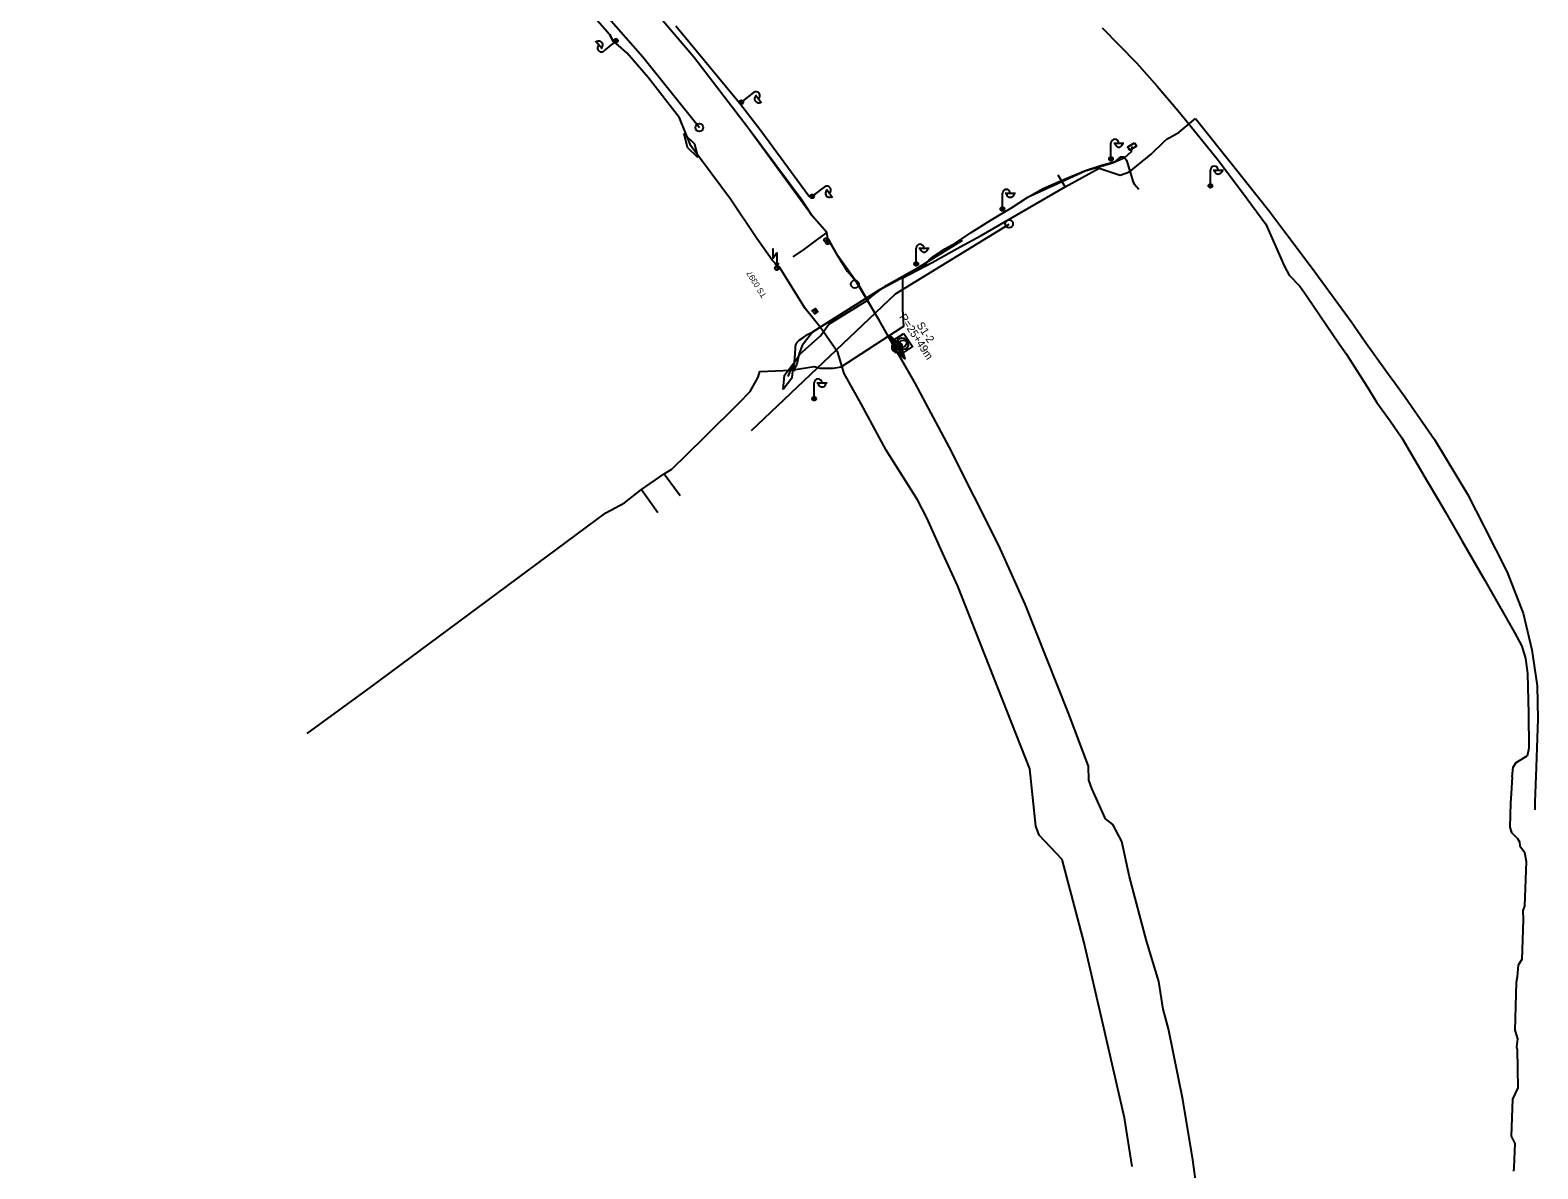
# Model space of a CAD drawing. Extents: x -748507 to -687366, y -1057342 to -1024924.
# Drawn here: x -744119.8 to -743736.3, y -1038215.5 to -1037925.9 of the extents above; entities that cross this region are included whole.
import ezdxf

# ---------------------------------------------------------------- set-up
doc = ezdxf.new("R2010")
doc.units = 0
for name, color, linetype in [('6kV - SŽDC', 7, 'Continuous'), ('DK + TKK - SŽDC', 7, 'Continuous'), ('Kanalizace - pražské vodovody a kanalizace', 7, 'Continuous'), ('kanalizace ČD', 7, 'Continuous'), ('PRE - NN', 7, 'Continuous'), ('PRE - VN', 7, 'Continuous'), ('STL - PRAŽSKÁ PLYNÁRENSKÁ', 7, 'Continuous'), ('TK+DOK_Pha Holešovice - Kralupy', 7, 'Continuous'), ('Vedení NN - SŽDC', 7, 'Continuous'), ('ČD-Telematika_DK+TKK', 7, 'Continuous')]:
    doc.layers.add(name, color=color, linetype=linetype)

msp = doc.modelspace()

# ---------------------------------------------------------------- linework, layer by layer
at = {"layer": '6kV - SŽDC'}
for p, q in [((-743930.89, -1037981.43), (-743930.89, -1037983.93)), ((-743930.89, -1037983.93), (-743929.89, -1037982.43)), ((-743929.89, -1037982.43), (-743929.89, -1037985.93)), ((-743930.39, -1037985.03), (-743929.89, -1037985.93)), ((-743929.94, -1037986.43), (-743929.84, -1037986.43)), ((-743929.89, -1037985.93), (-743929.39, -1037985.03))]:
    msp.add_line(p, q, dxfattribs=at)
for points in [[(-743989.74, -1037907.17), (-743972.42, -1037926.86), (-743971.51, -1037928.66), (-743970.83, -1037928.59)], [(-743929.38, -1037986.08), (-743931.03, -1037984.4), (-743934.99, -1037978.89), (-743941.71, -1037968.88), (-743951.72, -1037955.26), (-743954.61, -1037948.2), (-743962.61, -1037937.94), (-743968.04, -1037931.62), (-743970.13, -1037929.74), (-743971.51, -1037928.66), (-743972.42, -1037926.86)], [(-743950.01, -1037958.31), (-743952.59, -1037955.75), (-743953.43, -1037952.21), (-743950.85, -1037954.77), (-743950.01, -1037958.31)], [(-743857.28, -1038136.85), (-743863.19, -1038130.67), (-743864.02, -1038128.37), (-743865.55, -1038113.76), (-743883.85, -1038067.27), (-743887.69, -1038059), (-743891.71, -1038049.93), (-743894.08, -1038045.32), (-743902.07, -1038032.69), (-743908.42, -1038020.92), (-743912.76, -1038013.22), (-743914.38, -1038007.84), (-743918.81, -1038001.48), (-743922.64, -1037996.66), (-743929.22, -1037986.18), (-743929.38, -1037986.08), (-743929.89, -1037986.43)], [(-743839.49, -1038214.96), (-743841.42, -1038202.51), (-743846.96, -1038178.59), (-743851.76, -1038158.03), (-743857.28, -1038136.85)]]:
    msp.add_lwpolyline(points, dxfattribs=at)
msp.add_circle((-743929.89, -1037986.43), 0.5, dxfattribs=at)
at = {"layer": 'DK + TKK - SŽDC'}
for p, q in [((-743917.4, -1037979.26), (-743917.3, -1037979.26)), ((-743917, -1037979.83), (-743916.9, -1037979.83))]:
    msp.add_line(p, q, dxfattribs=at)
for points in [[(-743917.13, -1037977.37), (-743920.94, -1037973.08), (-743923.44, -1037969.18), (-743937.32, -1037950.58), (-743951, -1037932.72), (-743961.3, -1037920.58)], [(-743916.89, -1037978.84), (-743917.13, -1037977.37), (-743919.84, -1037979.33), (-743922.93, -1037981.61), (-743925.83, -1037983.52)], [(-743916.89, -1037978.84), (-743917.35, -1037979.26)], [(-743916.52, -1037979.46), (-743916.95, -1037979.83)], [(-743873.45, -1038056.97), (-743885.94, -1038032.02), (-743894.72, -1038015.69), (-743903.85, -1037999.61), (-743909.08, -1037990.51), (-743909.69, -1037989.77), (-743911.87, -1037987.29), (-743914.4, -1037983.29), (-743916.52, -1037979.46), (-743916.89, -1037978.84)], [(-743831.59, -1038174.87), (-743832.72, -1038167.9), (-743835.86, -1038157.49), (-743840.18, -1038141.25), (-743842.11, -1038132.25), (-743844.44, -1038127.94), (-743846.27, -1038126.48), (-743849.8, -1038118.78), (-743850.55, -1038116.65), (-743850.63, -1038113.07), (-743855.68, -1038099.64), (-743866.71, -1038071.91), (-743873.45, -1038056.97)], [(-743817.1, -1038311.81), (-743817.13, -1038284.47), (-743817.99, -1038274.76), (-743819.12, -1038254.08), (-743820.54, -1038239.39), (-743824.11, -1038213.21), (-743826.65, -1038197.89), (-743830.31, -1038179.92), (-743831.59, -1038174.87)]]:
    msp.add_lwpolyline(points, dxfattribs=at)
for centre in [(-743917.35, -1037979.26), (-743916.95, -1037979.83)]:
    msp.add_circle(centre, 0.5, dxfattribs=at)
at = {"layer": 'Kanalizace - pražské vodovody a kanalizace'}
for p, q in [((-743899.68, -1037992.92), (-743870.82, -1037975.21)), ((-743936.35, -1038027.75), (-743899.68, -1037992.92))]:
    msp.add_line(p, q, dxfattribs=at)
at = {"layer": 'kanalizace ČD'}
for points in [[(-743949.52, -1037950.73), (-743963.98, -1037932.73), (-743980.01, -1037914.41), (-744006.76, -1037884.28), (-744040.1, -1037846.82), (-744073.37, -1037809.61), (-744104.79, -1037774.57), (-744106.99, -1037773.74), (-744108.26, -1037772.24), (-744108.47, -1037770.54), (-744119.79, -1037757.39)], [(-743919.85, -1037997.74), (-743920.24, -1037998.05), (-743920.86, -1037997.26), (-743920.08, -1037996.64), (-743919.46, -1037997.43), (-743919.85, -1037997.74), (-743920.47, -1037996.95)]]:
    msp.add_lwpolyline(points, dxfattribs=at)
for centre in [(-743949.59, -1037950.66), (-743870.82, -1037975.14), (-743910.04, -1037990.49)]:
    msp.add_circle(centre, 1, dxfattribs=at)
at = {"layer": 'PRE - NN'}
msp.add_lwpolyline([(-743892.02, -1037985.3), (-743893.69, -1037986.34), (-743894.53, -1037986.89), (-743903.77, -1037991.96), (-743920.7, -1038002.64), (-743922.31, -1038004.63), (-743923.42, -1038006.13), (-743924.23, -1038008.12), (-743924.83, -1038010.81), (-743925.27, -1038011.83), (-743925.57, -1038012.62)], dxfattribs=at)
at = {"layer": 'PRE - VN'}
msp.add_lwpolyline([(-743925.57, -1038012.62), (-743925.22, -1038008.25), (-743925.17, -1038006.67), (-743925.01, -1038005.76), (-743924.74, -1038005.22), (-743924.19, -1038004.71), (-743923.04, -1038004.01), (-743922.11, -1038003.32), (-743920.7, -1038002.64), (-743903.77, -1037991.96), (-743894.53, -1037986.89), (-743892.02, -1037985.3), (-743891.1, -1037984.31), (-743889.98, -1037983.33), (-743887.17, -1037981.48), (-743884.4, -1037980), (-743880.47, -1037977.38), (-743875.48, -1037974.2), (-743870.17, -1037971.04), (-743866.08, -1037968.38), (-743862.16, -1037966.18), (-743856.29, -1037963.57), (-743852.85, -1037962.16), (-743851.6, -1037961.67), (-743847.21, -1037960.18), (-743844.72, -1037959.57), (-743843.69, -1037959.18), (-743842.39, -1037958.09), (-743841.65, -1037958.11), (-743840.93, -1037958.97), (-743839.29, -1037964.56), (-743839.03, -1037964.98), (-743837.85, -1037966.29)], dxfattribs=at)
at = {"layer": 'STL - PRAŽSKÁ PLYNÁRENSKÁ'}
for p, q in [((-743856.54, -1037965.71), (-743858.32, -1037962.8)), ((-743958.55, -1038038.74), (-743954.48, -1038044.28)), ((-743964.3, -1038042.75), (-743960.19, -1038048.54))]:
    msp.add_line(p, q, dxfattribs=at)
for points in [[(-743956.62, -1038037.51), (-743952.7, -1038033.69), (-743948.13, -1038029.27), (-743939.44, -1038020.67), (-743936.7, -1038017.8), (-743934.61, -1038014.18), (-743934.19, -1038012.71), (-743926.27, -1038012.36), (-743920.43, -1038011.4), (-743918.88, -1038011.83), (-743915.57, -1038011.83), (-743913.53, -1038011.49), (-743898.03, -1038001.46), (-743897.61, -1038001.19), (-743897.68, -1038000), (-743897.86, -1037996.76), (-743897.82, -1037990.96), (-743897.81, -1037988.87), (-743890.34, -1037984.97), (-743883.23, -1037980.98), (-743877.91, -1037978.12), (-743856.54, -1037965.71), (-743847.88, -1037960.95), (-743842.53, -1037962.76), (-743840.23, -1037961.95), (-743834.71, -1037957.4), (-743831.33, -1037954.24), (-743830.6, -1037953.56), (-743829.73, -1037953.07), (-743827.59, -1037951.86), (-743823.4, -1037948.36)], [(-743823.4, -1037948.36), (-743813.29, -1037960.94), (-743804.73, -1037971.72), (-743801.16, -1037976.49), (-743799.89, -1037978.2), (-743793.75, -1037986.46), (-743784.53, -1037999.05), (-743783.85, -1038000), (-743780.4, -1038004.86), (-743774.42, -1038013.27), (-743773.92, -1038013.95), (-743772.73, -1038015.57), (-743770.06, -1038019.2), (-743762.59, -1038030.04), (-743754.22, -1038043.93), (-743750, -1038052.19), (-743744.12, -1038063.71), (-743740.74, -1038072.5), (-743740.09, -1038074.18), (-743737.83, -1038083.54), (-743736.54, -1038092.65), (-743736.33, -1038101.05), (-743736.75, -1038113.32), (-743737.1, -1038122.24), (-743737.12, -1038124), (-743737.18, -1038124.24)], [(-744049.38, -1038104.79), (-744033.05, -1038092.89), (-743973.35, -1038048.63), (-743968.66, -1038046.15), (-743964.3, -1038042.75), (-743958.55, -1038038.74), (-743956.62, -1038037.51)]]:
    msp.add_lwpolyline(points, dxfattribs=at)
at = {"layer": 'TK+DOK_Pha Holešovice - Kralupy'}
for p, q in [((-743901.11, -1038003.85), (-743900.99, -1038003.9)), ((-743900.89, -1038004.66), (-743900.44, -1038004.76)), ((-743900.64, -1038006.53), (-743899.97, -1038005.85)), ((-743900.5, -1038005.93), (-743899.55, -1038006.13)), ((-743900.48, -1038007.17), (-743899.57, -1038006.26)), ((-743899.07, -1038006.75), (-743898.14, -1038005.82)), ((-743898.34, -1038005.56), (-743898.34, -1038005.56)), ((-743898.34, -1038005.56), (-743898.34, -1038005.56)), ((-743896.96, -1038004.92), (-743896.95, -1038004.96)), ((-743900.26, -1038007.47), (-743900.26, -1038007.47)), ((-743900.26, -1038007.47), (-743900.26, -1038007.47)), ((-743900.23, -1038006.74), (-743898.97, -1038007.01)), ((-743899.77, -1038006.81), (-743899.29, -1038006.52)), ((-743898.83, -1038008.22), (-743898.08, -1038008.38)), ((-743898.66, -1038007.15), (-743897.95, -1038006.44)), ((-743898.33, -1038007.47), (-743898.33, -1038007.47)), ((-743897.68, -1038009.21), (-743897.53, -1038009.23))]:
    msp.add_line(p, q, dxfattribs=at)
for points in [[(-743899.77, -1038006.81), (-743903.85, -1037999.61), (-743909.69, -1037989.77), (-743914.4, -1037983.29), (-743916.89, -1037978.84), (-743917.13, -1037977.37), (-743920.94, -1037973.08), (-743923.44, -1037969.18), (-743937.32, -1037950.58), (-743951, -1037932.72), (-743961.3, -1037920.58)], [(-743850.63, -1038113.07), (-743855.68, -1038099.64), (-743866.71, -1038071.91), (-743873.45, -1038056.97), (-743885.94, -1038032.02), (-743894.72, -1038015.69), (-743899.77, -1038006.81), (-743903.85, -1037999.61), (-743909.08, -1037990.51), (-743909.69, -1037989.77), (-743911.87, -1037987.29), (-743914.4, -1037983.29), (-743916.89, -1037978.84), (-743917.13, -1037977.37), (-743920.94, -1037973.08), (-743937.32, -1037950.58), (-743951, -1037932.72), (-743961.3, -1037920.58)], [(-743901.21, -1038003.57), (-743898.43, -1038005.97), (-743897.37, -1038009.48)], [(-743900.24, -1038005.56), (-743899.3, -1038006.52), (-743900.26, -1038007.47)], [(-743898.34, -1038005.56), (-743899.29, -1038006.52), (-743898.33, -1038007.47)], [(-743820.54, -1038239.39), (-743824.11, -1038213.21), (-743826.65, -1038197.89), (-743830.31, -1038179.92), (-743831.59, -1038174.87), (-743832.72, -1038167.9), (-743835.86, -1038157.49), (-743840.18, -1038141.25), (-743842.11, -1038132.25), (-743844.44, -1038127.94), (-743846.27, -1038126.49), (-743849.8, -1038118.78), (-743850.55, -1038116.65), (-743850.63, -1038113.07), (-743855.68, -1038099.64), (-743866.71, -1038071.91), (-743873.45, -1038056.97), (-743885.94, -1038032.02), (-743894.72, -1038015.69), (-743899.77, -1038006.81)], [(-743817.13, -1038284.47), (-743818, -1038274.76), (-743819.12, -1038254.08), (-743820.54, -1038239.39), (-743824.11, -1038213.21), (-743826.65, -1038197.89), (-743830.31, -1038179.92), (-743831.59, -1038174.87), (-743832.72, -1038167.9), (-743835.86, -1038157.49), (-743840.18, -1038141.25), (-743842.11, -1038132.25), (-743844.44, -1038127.94), (-743846.27, -1038126.49), (-743849.8, -1038118.78), (-743850.55, -1038116.65), (-743850.63, -1038113.07)]]:
    msp.add_lwpolyline(points, dxfattribs=at)
for points in [[(-743901.21, -1038003.57), (-743900.14, -1038007.08), (-743897.37, -1038009.48)], [(-743897.59, -1038003.04), (-743895.42, -1038006.38), (-743898.2, -1038008.19), (-743900.37, -1038004.85)]]:
    msp.add_lwpolyline(points, close=True, dxfattribs=at)
for centre in [(-743898.08, -1038005.35), (-743897.7, -1038005.89)]:
    msp.add_circle(centre, 1.2, dxfattribs=at)
for centre, start, end in [((-743899.3, -1038006.52), 134.526, 224.763), ((-743899.29, -1038006.52), 45.4782, 134.8443), ((-743899.29, -1038006.52), 315.2412, 45.4782), ((-743899.3, -1038006.52), 224.7644, 315.5538)]:
    msp.add_arc(centre, 1.35, start, end, dxfattribs=at)
at = {"layer": 'Vedení NN - SŽDC'}
for p, q in [((-743974.31, -1037930.64), (-743975.99, -1037928.66)), ((-743971.19, -1037928.91), (-743973.86, -1037931.17)), ((-743970.32, -1037928.48), (-743971.28, -1037928.4)), ((-743970.39, -1037928.85), (-743971.27, -1037928.78)), ((-743939.42, -1037944.29), (-743938.47, -1037944.41)), ((-743939.34, -1037943.92), (-743938.47, -1037944.03)), ((-743938.54, -1037943.9), (-743935.77, -1037941.76)), ((-743935.34, -1037942.31), (-743933.75, -1037944.36)), ((-743844.9, -1037958.13), (-743844.9, -1037954.63)), ((-743844.2, -1037954.63), (-743841.6, -1037954.63)), ((-743845.38, -1037958.78), (-743844.76, -1037958.15)), ((-743845.14, -1037959.07), (-743844.46, -1037958.39)), ((-743819.61, -1037964.97), (-743819.61, -1037961.47)), ((-743818.91, -1037961.47), (-743816.31, -1037961.47)), ((-743921.31, -1037967.86), (-743920.44, -1037967.98)), ((-743920.5, -1037967.85), (-743917.7, -1037965.76)), ((-743917.28, -1037966.32), (-743915.73, -1037968.41)), ((-743872.51, -1037970.87), (-743872.51, -1037967.37)), ((-743871.81, -1037967.37), (-743869.21, -1037967.37)), ((-743820.09, -1037965.62), (-743819.47, -1037964.99)), ((-743819.85, -1037965.91), (-743819.17, -1037965.23)), ((-743921.4, -1037968.22), (-743920.45, -1037968.36)), ((-743872.99, -1037971.52), (-743872.37, -1037970.89)), ((-743872.75, -1037971.81), (-743872.07, -1037971.13)), ((-743894.44, -1037984.84), (-743894.44, -1037981.34)), ((-743893.74, -1037981.34), (-743891.14, -1037981.34)), ((-743894.92, -1037985.49), (-743894.3, -1037984.86)), ((-743894.68, -1037985.78), (-743894, -1037985.1)), ((-743920.39, -1038019.11), (-743920.39, -1038015.61)), ((-743919.69, -1038015.61), (-743917.09, -1038015.61)), ((-743920.87, -1038019.76), (-743920.25, -1038019.13)), ((-743920.63, -1038020.05), (-743919.95, -1038019.37))]:
    msp.add_line(p, q, dxfattribs=at)
for points in [[(-743920.93, -1037968.16), (-743921.75, -1037968.09), (-743933.93, -1037951.48), (-743939.42, -1037944.46), (-743955.58, -1037924.89)], [(-743939.42, -1037944.46), (-743938.89, -1037944.18)], [(-743865.37, -1037968), (-743851.48, -1037961.66), (-743844.47, -1037959.62), (-743841.41, -1037958.28), (-743839.66, -1037956.76), (-743839.51, -1037955.49)], [(-743838.92, -1037954.54), (-743838.4, -1037955.4), (-743840.1, -1037956.44), (-743840.62, -1037955.58), (-743838.92, -1037954.54)], [(-743905.82, -1037993.64), (-743902.1, -1037990.83), (-743893.77, -1037986.13), (-743882.63, -1037979.32)], [(-743927, -1038013.99), (-743925.72, -1038010.8), (-743924.03, -1038008.31), (-743918.81, -1038003.59), (-743916.68, -1038000.66), (-743906.93, -1037994.65), (-743905.82, -1037993.64)], [(-743916.68, -1038000.66), (-743906.93, -1037994.65)], [(-743928.3, -1038017.24), (-743927.93, -1038013.62), (-743925.7, -1038010.74), (-743926.07, -1038014.36), (-743928.3, -1038017.24)]]:
    msp.add_lwpolyline(points, dxfattribs=at)
for centre in [(-743970.81, -1037928.58), (-743970.81, -1037928.58), (-743938.93, -1037944.21), (-743938.93, -1037944.21), (-743844.9, -1037958.63), (-743844.9, -1037958.63), (-743920.91, -1037968.15), (-743920.91, -1037968.15), (-743819.61, -1037965.47), (-743819.61, -1037965.47), (-743872.51, -1037971.37), (-743872.51, -1037971.37), (-743894.44, -1037985.34), (-743894.44, -1037985.34), (-743920.39, -1038019.61), (-743920.39, -1038019.61)]:
    msp.add_circle(centre, 0.5, dxfattribs=at)
for centre, start, end in [((-743975.14, -1037929.64), 309.6397, 131.0449), ((-743974.51, -1037930.41), 130.3423, 310.3423), ((-743935.16, -1037942.55), 307.8468, 127.8468), ((-743934.55, -1037943.34), 127.1442, 308.5494), ((-743843.9, -1037954.63), 0, 180), ((-743842.9, -1037954.64), 179.2974, 0.7026), ((-743818.61, -1037961.47), 0, 180), ((-743817.61, -1037961.48), 179.2974, 0.7026), ((-743917.1, -1037966.56), 306.7104, 126.7104), ((-743916.51, -1037967.37), 126.0078, 307.4129), ((-743871.51, -1037967.37), 0, 180), ((-743870.51, -1037967.38), 179.2974, 0.7026), ((-743893.44, -1037981.34), 0, 180), ((-743892.44, -1037981.35), 179.2974, 0.7026), ((-743919.39, -1038015.61), 0, 180), ((-743918.39, -1038015.62), 179.2974, 0.7026)]:
    msp.add_arc(centre, 1, start, end, dxfattribs=at)
at = {"layer": 'ČD-Telematika_DK+TKK'}
for points in [[(-743847.16, -1037925.27), (-743838.45, -1037934.17), (-743833.12, -1037940.13), (-743827.82, -1037946.42), (-743824.78, -1037950.11)], [(-743824.78, -1037950.11), (-743817.56, -1037959.01), (-743810.23, -1037968.79), (-743805.49, -1037975.19), (-743800.76, -1037986.01), (-743799.54, -1037988.19), (-743796.85, -1037990.97), (-743795.12, -1037993.5), (-743786.86, -1038005.66), (-743784.98, -1038008.31)], [(-743784.98, -1038008.31), (-743784.18, -1038009.69), (-743779.85, -1038016.47), (-743777.27, -1038020.55), (-743773.89, -1038025.23), (-743770.96, -1038029.57), (-743764.48, -1038040.63), (-743761.57, -1038045.41), (-743759.83, -1038048.52), (-743755.54, -1038055.85), (-743749.91, -1038065.68), (-743742.23, -1038079.05), (-743740.42, -1038082.55), (-743739.46, -1038085.67), (-743738.94, -1038089.54), (-743738.72, -1038099.74), (-743738.66, -1038108.51), (-743739.02, -1038110.52)], [(-743742.83, -1038115.84), (-743742.64, -1038113.35), (-743741.81, -1038112.12), (-743739.01, -1038110.48)], [(-743742.83, -1038115.84), (-743743.13, -1038120.06), (-743743.25, -1038122.5), (-743743.43, -1038128.65), (-743743.06, -1038129.97), (-743741.51, -1038131.53), (-743740.98, -1038132.34), (-743740.87, -1038133.38), (-743739.71, -1038134.93), (-743739.34, -1038137.3), (-743739.71, -1038148.73), (-743740.18, -1038149.78), (-743740.1, -1038152.14), (-743740.39, -1038162.28)], [(-743740.39, -1038162.28), (-743741.3, -1038163.67), (-743741.56, -1038166.68), (-743741.83, -1038168.09), (-743742.17, -1038180.28), (-743741.47, -1038182.44), (-743741.79, -1038184.47), (-743741.61, -1038185.12), (-743741.43, -1038194.94)], [(-743741.43, -1038194.94), (-743742.78, -1038197.83), (-743743.08, -1038207.17), (-743742.22, -1038209.08)], [(-743742.22, -1038209.08), (-743742.45, -1038215.17), (-743742.5, -1038216.08)]]:
    msp.add_lwpolyline(points, dxfattribs=at)

# ---------------------------------------------------------------- texts
at = {"layer": '6kV - SŽDC'}
msp.add_text('TS 0397', height=1.5, rotation=122.1232, dxfattribs=at).set_placement((-743932.41, -1037993.36))
at = {"layer": 'TK+DOK_Pha Holešovice - Kralupy'}
for s, p in [('R=25+49m', (-743898.85, -1037998.83)), ('S1-2', (-743894.43, -1038000.9))]:
    msp.add_text(s, height=2, rotation=303.0238, dxfattribs=at).set_placement(p)

doc.saveas('drawing.dxf')
